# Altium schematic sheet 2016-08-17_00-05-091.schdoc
size 469 x 147 mm; SheetNumber: 1; SheetTotal: 1
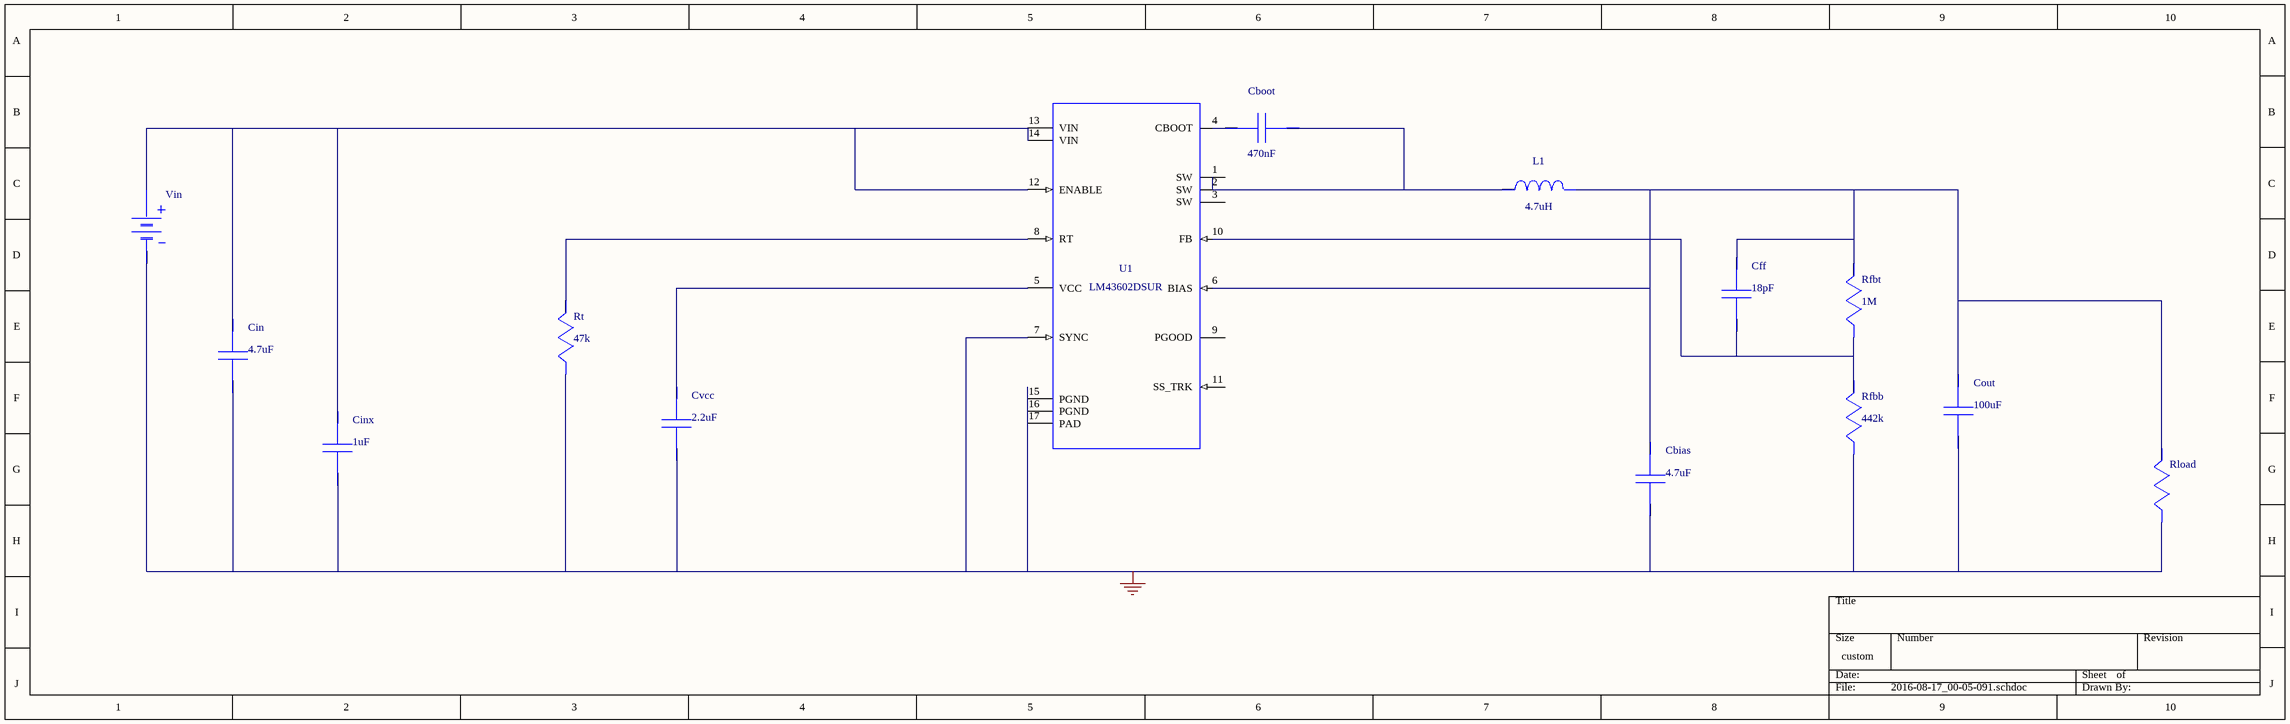
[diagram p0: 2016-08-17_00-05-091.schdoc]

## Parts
Cbias  value 4.7uF  (hidden comment: GRM188R60J475KE19D)
Cboot  value 470nF  (hidden comment: GRM188R70J474KA01D)
Cff  value 18pF  (hidden comment: C0805C180M3GACTU)
Cin  value 4.7uF  (hidden comment: GRM31CR71H475KA12L)
Cinx  value 1uF  (hidden comment: C3216X5R1H105K)
Cout  value 100uF  (hidden comment: GRM31CR60J107ME39L)
Cvcc  value 2.2uF  (hidden comment: GRM188R60J225KE19D)
L1  value 4.7uH  (hidden comment: SRN6045-4R7Y)
Rfbb  value 442k  (hidden comment: RC0603FR-07442KL)
Rfbt  value 1M  (hidden comment: CRCW06031M00FKEA)
Rload  WB_LOAD_RESISTOR  (value not drawn)
Rt  value 47k  (hidden comment: RC0603FR-0747KL)
U1  LM43602DSUR
Vin  WB_BATTERY  (value not drawn)

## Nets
0: Cbias.2 Cin.2 Cinx.2 Cout.2 Cvcc.2 Rfbb.2 Rload.2 Rt.2 U1.7(SYNC) U1.15(PGND) U1.16(PGND) U1.17(PAD) Vin.2(-)
NetCbias_1: Cbias.1 Cff.1 Cout.1 L1.2 Rfbt.1 Rload.1 U1.6(BIAS)
NetCboot_1: Cboot.1 L1.1 U1.2(SW)
NetCboot_2: Cboot.2 U1.4(CBOOT)
NetCff_2: Cff.2 Rfbb.1 Rfbt.2 U1.10(FB)
NetCin_1: Cin.1 Cinx.1 U1.12(ENABLE) U1.13(VIN) U1.14(VIN) Vin.1(+)
NetCvcc_1: Cvcc.1 U1.5(VCC)
NetRt_1: Rt.1 U1.8(RT)

Not connected (* = marked no-connect by the designer): U1 1(SW) 3(SW) 9(PGOOD) 11(SS_TRK)

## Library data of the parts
Cbias = GRM188R60J475KE19D: GRM188R60J475KE1; Manufacturer Name: MuRata
Cboot = GRM188R70J474KA01D: GRM188R70J474KA0; Manufacturer Name: MuRata
Cff = C0805C180M3GACTU: Manufacturer Name: Kemet
Cin = GRM31CR71H475KA12L: GRM31CR71H475KA1; Manufacturer Name: MuRata
Cinx = C3216X5R1H105K: Manufacturer Name: TDK
Cout = GRM31CR60J107ME39L: GRM31CR60J107ME3; Manufacturer Name: MuRata
Cvcc = GRM188R60J225KE19D: GRM188R60J225KE1; Manufacturer Name: MuRata
L1 = SRN6045-4R7Y: Manufacturer Name: Bourns
Rfbb = RC0603FR-07442KL: Manufacturer Name: Yageo America
Rfbt = CRCW06031M00FKEA: Manufacturer Name: Vishay-Dale
Rt = RC0603FR-0747KL: Manufacturer Name: Yageo America
U1 = LM43602DSUR: Manufacturer Name: Texas Instruments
